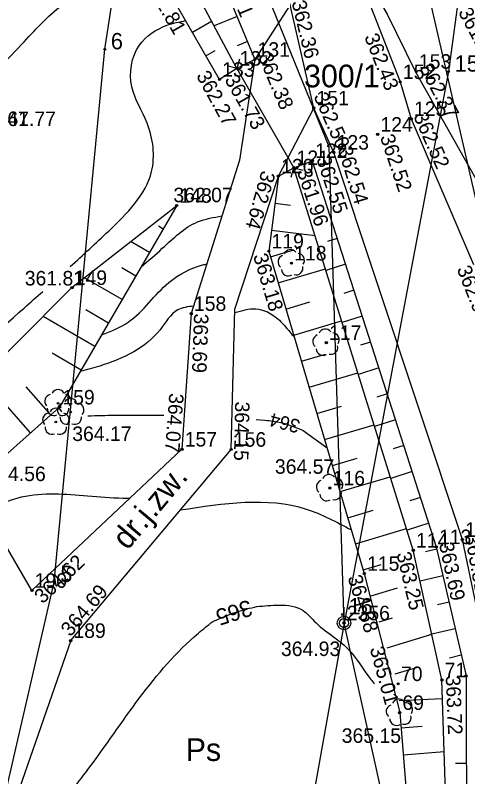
# Model space of a CAD drawing. Extents: x 4635329 to 4651863, y 5356628 to 5367582.
# Drawn here: x 4651721.4 to 4651746.37, y 5357073.31 to 5357115.3 of the extents above; entities that cross this region are included whole.
import ezdxf

# ---------------------------------------------------------------- set-up
doc = ezdxf.new("R2010")
doc.units = 0
for name, color, linetype in [('Level 12', 7, 'Continuous'), ('Level 2', 7, 'Continuous'), ('Level 20', 7, 'Continuous'), ('Level 21', 7, 'Continuous'), ('Level 24', 7, 'Continuous'), ('Level 4', 7, 'Continuous'), ('Level 44', 7, 'Continuous'), ('Level 45', 7, 'Continuous'), ('Level 46', 7, 'Continuous'), ('Level 47', 7, 'Continuous'), ('Level 48', 7, 'Continuous'), ('Level 5', 7, 'Continuous'), ('Level 55', 7, 'Continuous'), ('Level 62', 7, 'Continuous'), ('Level 63', 7, 'Continuous'), ('Level 7', 7, 'Continuous')]:
    doc.layers.add(name, color=color, linetype=linetype)

msp = doc.modelspace()

# ---------------------------------------------------------------- linework, layer by layer
at = {"layer": 'Level 2'}
for p, q in [((4651752.271, 5357081.395), (4651734.633, 5357158.117)), ((4651739.54, 5357082.165), (4651739.54, 5357082.665))]:
    msp.add_line(p, q, dxfattribs=at)
msp.add_circle((4651739.54, 5357081.79), 0.375, dxfattribs=at)
at = {"layer": 'Level 20'}
for p, q in [((4651740.22, 5357117.83), (4651742.64, 5357111.63)), ((4651742.64, 5357111.63), (4651743.25, 5357109.59)), ((4651743.25, 5357109.59), (4651746.68, 5357101.55))]:
    msp.add_line(p, q, dxfattribs=at)
for points in [[(4651729.32, 5357025.03), (4651737.42, 5357039.16), (4651742.88, 5357049.73), (4651744.63, 5357054), (4651745.586, 5357056.87), (4651746.84, 5357061.68), (4651747.431, 5357065.159), (4651747.81, 5357068.95), (4651747.54, 5357079.35), (4651746.07, 5357086.39), (4651738.98, 5357107.74), (4651737.87, 5357110.18), (4651736.57, 5357115.87), (4651735.37, 5357118.93)], [(4651736.57, 5357115.87), (4651734.62, 5357112.86), (4651733.779, 5357107.317), (4651731.11, 5357098.85), (4651730.6, 5357091.37), (4651722.32, 5357083.58)], [(4651724.46, 5357080.82), (4651733.31, 5357091.36), (4651733.521, 5357099.085), (4651735.92, 5357106.43), (4651737.87, 5357110.18)], [(4651722.32, 5357083.58), (4651718.95, 5357089.36)], [(4651724.46, 5357080.82), (4651721.17, 5357071.37)]]:
    msp.add_lwpolyline(points, dxfattribs=at)
at = {"layer": 'Level 24'}
for p, q in [((4651733.769, 5357112.882), (4651733.63, 5357112.37)), ((4651733.63, 5357112.37), (4651733.118, 5357112.509)), ((4651733.63, 5357112.37), (4651736.77, 5357106.89)), ((4651736.631, 5357106.378), (4651736.77, 5357106.89)), ((4651736.77, 5357106.89), (4651737.282, 5357106.751))]:
    msp.add_line(p, q, dxfattribs=at)
at = {"layer": 'Level 4'}
for p, q in [((4651747.779, 5357130.661), (4651745.31, 5357112.19)), ((4651738.719, 5357108.044), (4651734.382, 5357118.748)), ((4651726.34, 5357113.42), (4651726.932, 5357117.207)), ((4651723.55, 5357084.05), (4651726.34, 5357113.42)), ((4651745.31, 5357112.19), (4651739.54, 5357081.79)), ((4651739.54, 5357081.79), (4651738.719, 5357108.044)), ((4651714.1, 5357043.07), (4651723.55, 5357084.05)), ((4651739.54, 5357081.79), (4651731.74, 5357037.85)), ((4651742.153, 5357070.018), (4651739.54, 5357081.79))]:
    msp.add_line(p, q, dxfattribs=at)
at = {"layer": 'Level 44'}
for centre in [(4651734.62, 5357112.86), (4651733.63, 5357112.37), (4651743.52, 5357112.2), (4651732.67, 5357111.76), (4651742.64, 5357111.63), (4651737.87, 5357110.18), (4651743.25, 5357109.59), (4651741.4, 5357108.73), (4651738.98, 5357107.74), (4651737.79, 5357107.28), (4651736.77, 5357106.89), (4651735.92, 5357106.43), (4651730.31, 5357104.81), (4651735.39, 5357102.29), (4651736.64, 5357101.63), (4651724.53, 5357100.28), (4651731.11, 5357098.85), (4651738.56, 5357097.25), (4651723.85, 5357093.69), (4651730.6, 5357091.37), (4651733.31, 5357091.36), (4651738.76, 5357089.23), (4651746.07, 5357086.39), (4651744.63, 5357085.99), (4651743.36, 5357085.8), (4651740.66, 5357084.52), (4651722.32, 5357083.58), (4651739.54, 5357081.79), (4651739.54, 5357081.79), (4651739.54, 5357081.79), (4651739.54, 5357081.79), (4651739.54, 5357081.79), (4651739.54, 5357081.79), (4651724.46, 5357080.82), (4651746.27, 5357078.87), (4651742.53, 5357078.44), (4651744.94, 5357078.65), (4651742.61, 5357076.85)]:
    msp.add_circle(centre, 0.04, dxfattribs=at)
at = {"layer": 'Level 46'}
for p, q in [((4651734.697, 5357093.013), (4651735.173, 5357092.969)), ((4651737.283, 5357092.406), (4651738.608, 5357091.439))]:
    msp.add_line(p, q, dxfattribs=at)
for points in [[(4651715.922, 5357108.895), (4651718.598, 5357110.718), (4651721.751, 5357113.69), (4651723.994, 5357115.873), (4651726.419, 5357117.329), (4651727.935, 5357117.996), (4651728.782, 5357118.194)], [(4651724.435, 5357101.441), (4651726.557, 5357103.402), (4651728.921, 5357106.677), (4651728.679, 5357109.346), (4651727.83, 5357111.348), (4651728.254, 5357113.652), (4651729.77, 5357114.744), (4651730.809, 5357115.004)], [(4651728.346, 5357101.43), (4651729.515, 5357102.448), (4651731.455, 5357103.904), (4651732.807, 5357104.233)], [(4651726.162, 5357097.67), (4651727.635, 5357098.384), (4651729.879, 5357100.568), (4651731.758, 5357101.538), (4651731.973, 5357101.588)], [(4651710.095, 5357097.843), (4651710.307, 5357097.883), (4651713.763, 5357097.458), (4651716.734, 5357096.306), (4651721.888, 5357099.157), (4651722.918, 5357100.066)], [(4651731.239, 5357099.261), (4651730.364, 5357099.051), (4651729.394, 5357097.96), (4651727.939, 5357096.747), (4651726.059, 5357095.958), (4651724.99, 5357095.653)], [(4651733.516, 5357098.902), (4651734.669, 5357099.112), (4651735.881, 5357098.566), (4651736.548, 5357097.838), (4651736.79, 5357097.569)], [(4651729.603, 5357093.229), (4651726.908, 5357093.229), (4651725.408, 5357093.193)], [(4651735.173, 5357092.969), (4651735.639, 5357092.926), (4651737.283, 5357092.406)], [(4651719.746, 5357087.994), (4651721.754, 5357088.741), (4651725.392, 5357088.801), (4651727.332, 5357088.68), (4651727.741, 5357088.68)], [(4651730.506, 5357088.021), (4651737.458, 5357088.073), (4651739.948, 5357086.92)], [(4651732.299, 5357081.873), (4651734.171, 5357082.566), (4651734.736, 5357082.695)], [(4651734.736, 5357082.695), (4651735.959, 5357082.779), (4651737.293, 5357082.475), (4651737.891, 5357081.899), (4651739.771, 5357080.352), (4651741.014, 5357078.684), (4651741.22, 5357078.439)], [(4651723.473, 5357071.251), (4651725.409, 5357073.711), (4651731.503, 5357081.232), (4651732.299, 5357081.873)]]:
    msp.add_spline(points, degree=3, dxfattribs=at)
at = {"layer": 'Level 48'}
for p, q in [((4651731.177, 5357114.362), (4651732.233, 5357114.968)), ((4651733.637, 5357115.238), (4651732.368, 5357114.713)), ((4651734.21, 5357113.852), (4651733.642, 5357113.617)), ((4651731.924, 5357113.061), (4651732.43, 5357113.352)), ((4651735.73, 5357104.942), (4651736.588, 5357104.832)), ((4651729.557, 5357103.513), (4651729.298, 5357103.663)), ((4651735.539, 5357103.454), (4651737.939, 5357103.147)), ((4651728.803, 5357102.216), (4651727.768, 5357102.817)), ((4651739.166, 5357102.996), (4651738.63, 5357102.823)), ((4651735.483, 5357101.977), (4651736.774, 5357102.36)), ((4651739.625, 5357101.568), (4651738.542, 5357101.219)), ((4651728.05, 5357100.919), (4651727.273, 5357101.37)), ((4651735.909, 5357100.539), (4651738.513, 5357101.311)), ((4651727.296, 5357099.622), (4651725.225, 5357100.825)), ((4651740.084, 5357100.139), (4651739.537, 5357099.964)), ((4651736.336, 5357099.101), (4651737.648, 5357099.49)), ((4651726.543, 5357098.325), (4651725.288, 5357099.054)), ((4651725.789, 5357097.028), (4651722.936, 5357098.686)), ((4651740.543, 5357098.711), (4651739.437, 5357098.356)), ((4651736.762, 5357097.663), (4651739.408, 5357098.448)), ((4651741.002, 5357097.283), (4651740.443, 5357097.104)), ((4651725.036, 5357095.731), (4651723.437, 5357096.66)), ((4651737.189, 5357096.225), (4651738.522, 5357096.62)), ((4651741.461, 5357095.855), (4651740.331, 5357095.492)), ((4651722.247, 5357092.273), (4651719.562, 5357095.312)), ((4651737.615, 5357094.787), (4651740.303, 5357095.584)), ((4651723.371, 5357093.266), (4651721.997, 5357094.82)), ((4651741.919, 5357094.427), (4651741.349, 5357094.244)), ((4651738.042, 5357093.349), (4651739.396, 5357093.75)), ((4651738.468, 5357091.911), (4651741.198, 5357092.72)), ((4651742.378, 5357092.999), (4651741.226, 5357092.629)), ((4651742.837, 5357091.571), (4651742.255, 5357091.384)), ((4651738.895, 5357090.473), (4651740.27, 5357090.88)), ((4651739.321, 5357089.034), (4651742.093, 5357089.856)), ((4651743.296, 5357090.143), (4651742.121, 5357089.765)), ((4651743.755, 5357088.715), (4651743.162, 5357088.524)), ((4651739.748, 5357087.596), (4651741.144, 5357088.01)), ((4651744.213, 5357087.287), (4651743.016, 5357086.902)), ((4651740.174, 5357086.158), (4651742.988, 5357086.993)), ((4651744.661, 5357085.855), (4651744.036, 5357085.711)), ((4651740.601, 5357084.72), (4651741.591, 5357085.014)), ((4651744.998, 5357084.394), (4651743.735, 5357084.103)), ((4651741.04, 5357083.286), (4651742.483, 5357083.73)), ((4651745.334, 5357082.932), (4651744.697, 5357082.785)), ((4651741.481, 5357081.852), (4651742.213, 5357082.077)), ((4651745.671, 5357081.47), (4651744.382, 5357081.173)), ((4651741.922, 5357080.418), (4651744.382, 5357081.175)), ((4651746.008, 5357080.008), (4651745.357, 5357079.859)), ((4651742.362, 5357078.985), (4651743.535, 5357079.345)), ((4651742.577, 5357077.511), (4651744.973, 5357077.632)), ((4651742.679, 5357076.015), (4651743.849, 5357076.111)), ((4651742.802, 5357074.52), (4651745.068, 5357074.706)), ((4651746.28, 5357074.038), (4651745.685, 5357074.037))]:
    msp.add_line(p, q, dxfattribs=at)
for points in [[(4651739.34, 5357119.79), (4651741.917, 5357115.357), (4651743.483, 5357112.18), (4651749.82, 5357100.94)], [(4651730.58, 5357118.08), (4651733.63, 5357112.336)], [(4651732.49, 5357118.01), (4651734.62, 5357112.86)], [(4651732.67, 5357111.76), (4651729.4, 5357117.46)], [(4651734.62, 5357112.86), (4651733.63, 5357112.37), (4651732.67, 5357111.76)], [(4651735.92, 5357106.43), (4651736.77, 5357106.89), (4651737.79, 5357107.28)], [(4651737.79, 5357107.28), (4651744.63, 5357085.99), (4651746.27, 5357078.87), (4651746.29, 5357069.02), (4651745.52, 5357061.26), (4651742.88, 5357054.46)], [(4651741.87, 5357054.91), (4651743.95, 5357061.2), (4651745.25, 5357069.08), (4651744.94, 5357078.65), (4651743.36, 5357085.8), (4651736.77, 5357106.89)], [(4651735.92, 5357106.43), (4651735.39, 5357102.29), (4651740.66, 5357084.52), (4651742.61, 5357076.85), (4651743.21, 5357069.57), (4651741.89, 5357061.31), (4651740.55, 5357055.11)], [(4651703.21, 5357089.09), (4651718.35, 5357094.1), (4651724.53, 5357100.28), (4651730.31, 5357104.81)], [(4651730.31, 5357104.81), (4651723.85, 5357093.69), (4651718.95, 5357089.36), (4651717.03, 5357087.37), (4651705.66, 5357084.24)]]:
    msp.add_lwpolyline(points, dxfattribs=at)
at = {"layer": 'Level 55'}
for centre in [(4651736.64, 5357101.63), (4651738.56, 5357097.25), (4651723.764, 5357093.907), (4651724.461, 5357093.421), (4651723.643, 5357092.876), (4651738.76, 5357089.23), (4651742.61, 5357076.85)]:
    msp.add_circle(centre, 0.045, dxfattribs=at)
for centre, start, end in [((4651736.589, 5357102.002), 37.8655, 157.6473), ((4651736.271, 5357101.697), 109.9556, 229.607), ((4651736.978, 5357101.793), 325.8648, 85.6487), ((4651736.463, 5357101.3), 181.9043, 301.61), ((4651736.899, 5357101.359), 253.9073, 13.5587), ((4651738.509, 5357097.622), 37.8655, 157.6473), ((4651738.898, 5357097.413), 325.8648, 85.6487), ((4651738.191, 5357097.317), 109.9556, 229.607), ((4651738.383, 5357096.92), 181.9043, 301.61), ((4651738.819, 5357096.979), 253.9073, 13.5587), ((4651723.407, 5357094.022), 102.1502, 221.8016), ((4651723.764, 5357094.282), 30.1471, 149.8529), ((4651724.12, 5357094.022), 318.1985, 77.8498), ((4651724.461, 5357093.796), 30.1471, 149.8529), ((4651723.543, 5357093.603), 174.1076, 293.8916), ((4651723.643, 5357093.251), 30.1471, 149.8529), ((4651724.105, 5357093.537), 102.1502, 221.8016), ((4651723.984, 5357093.603), 246.1084, 5.8902), ((4651724.818, 5357093.537), 318.1985, 77.8498), ((4651723.286, 5357092.992), 102.1502, 221.8016), ((4651724.241, 5357093.118), 174.1076, 293.8916), ((4651723.999, 5357092.992), 318.1985, 77.8498), ((4651724.682, 5357093.118), 246.1084, 5.8902), ((4651723.422, 5357092.572), 174.1076, 293.8916), ((4651723.863, 5357092.572), 246.1084, 5.8902), ((4651738.709, 5357089.602), 37.8655, 157.6473), ((4651739.098, 5357089.393), 325.8648, 85.6487), ((4651738.391, 5357089.297), 109.9556, 229.607), ((4651739.019, 5357088.959), 253.9073, 13.5587), ((4651738.583, 5357088.9), 181.9043, 301.61), ((4651742.559, 5357077.222), 37.8655, 157.6473), ((4651742.241, 5357076.917), 109.9556, 229.607), ((4651742.948, 5357077.013), 325.8648, 85.6487), ((4651742.433, 5357076.52), 181.9043, 301.61), ((4651742.869, 5357076.579), 253.9073, 13.5587)]:
    msp.add_arc(centre, 0.375, start, end, dxfattribs=at)
at = {"layer": 'Level 62'}
for centre in [(4651726.34, 5357113.42), (4651745.31, 5357112.19), (4651723.55, 5357084.05), (4651739.45, 5357082.26)]:
    msp.add_circle(centre, 0.05, dxfattribs=at)
at = {"layer": 'Level 63'}
for centre in [(4651734.62, 5357112.86), (4651733.63, 5357112.37), (4651743.52, 5357112.2), (4651732.67, 5357111.76), (4651742.64, 5357111.63), (4651737.87, 5357110.18), (4651743.25, 5357109.59), (4651741.4, 5357108.73), (4651738.98, 5357107.74), (4651737.79, 5357107.28), (4651736.77, 5357106.89), (4651735.92, 5357106.43), (4651730.31, 5357104.81), (4651735.39, 5357102.29), (4651736.64, 5357101.63), (4651724.53, 5357100.28), (4651731.11, 5357098.85), (4651738.56, 5357097.25), (4651723.85, 5357093.69), (4651730.6, 5357091.37), (4651733.31, 5357091.36), (4651738.76, 5357089.23), (4651746.07, 5357086.39), (4651744.63, 5357085.99), (4651743.36, 5357085.8), (4651740.66, 5357084.52), (4651722.32, 5357083.58), (4651739.54, 5357081.79), (4651739.54, 5357081.79), (4651739.54, 5357081.79), (4651739.54, 5357081.79), (4651739.54, 5357081.79), (4651739.54, 5357081.79), (4651724.46, 5357080.82), (4651746.27, 5357078.87), (4651742.53, 5357078.44), (4651744.94, 5357078.65), (4651742.61, 5357076.85)]:
    msp.add_circle(centre, 0.06, dxfattribs=at)
at = {"layer": 'Level 7'}
msp.add_circle((4651739.54, 5357081.79), 0.25, dxfattribs=at)

# ---------------------------------------------------------------- texts
at = {"layer": 'Level 12'}
msp.add_text('Ps', height=1.25, dxfattribs=at).set_placement((4651730.808, 5357074.185))
at = {"layer": 'Level 21'}
msp.add_text('dr.j.zw.', height=1.25, rotation=49.9812, dxfattribs=at).set_placement((4651727.594, 5357085.762))
at = {"layer": 'Level 45'}
for s, rotation, p in [('362.01', 292.5802, (4651732.591, 5357118.141)), ('361.81', 299.8433, (4651728.55, 5357116.995)), ('362.36', 283.4045, (4651736.644, 5357116.025)), ('361.90', 298.0066, (4651745.82, 5357115.477)), ('362.43', 291.4894, (4651740.646, 5357114.114)), ('362.38', 292.8028, (4651734.783, 5357113.031)), ('362.37', 298.3952, (4651743.669, 5357112.38)), ('362.27', 298.7971, (4651731.363, 5357111.97)), ('361.73', 299.6637, (4651732.925, 5357111.752)), ('362.50', 293.8537, (4651737.845, 5357110.836)), ('362.52', 293.7851, (4651743.349, 5357109.743)), ('362.52', 288.6135, (4651741.515, 5357108.589)), ('362.54', 287.1321, (4651739.184, 5357107.93)), ('362.55', 288.1825, (4651738.003, 5357107.39)), ('362.64', 253.9851, (4651735.001, 5357106.777)), ('361.96', 288.1543, (4651736.936, 5357106.7)), ('363.18', 286.4293, (4651734.516, 5357102.041)), ('362.97', 291.4587, (4651745.747, 5357101.319)), ('363.69', 267.9606, (4651731.267, 5357098.862)), ('364.07', 265.6562, (4651729.905, 5357094.483)), ('364.15', 268.7625, (4651733.533, 5357094.009)), ('363.81', 280.4303, (4651746.199, 5357086.616)), ('363.69', 282.1308, (4651744.774, 5357086.155)), ('363.25', 283.3157, (4651742.427, 5357085.618)), ('364.62', 43.1705, (4651722.911, 5357082.812)), ('364.68', 287.246, (4651739.731, 5357084.304)), ('364.69', 49.6034, (4651724.444, 5357080.993)), ('365.01', 285.2533, (4651740.955, 5357080.381)), ('363.72', 272.3884, (4651745.148, 5357078.881))]:
    msp.add_text(s, height=0.8, rotation=rotation, dxfattribs=at).set_placement(p)
for s, p in [('361.77', (4651720.37, 5357109.19)), ('362.07', (4651730.126, 5357104.99)), ('361.81', (4651721.925, 5357100.4)), ('364.17', (4651724.545, 5357091.825)), ('364.57', (4651735.727, 5357090.017)), ('364.56', (4651719.812, 5357089.616)), ('364.93', (4651736.059, 5357079.97)), ('365.15', (4651739.413, 5357075.182))]:
    msp.add_text(s, height=0.8, dxfattribs=at).set_placement(p)
at = {"layer": 'Level 47'}
for s, height, rotation, p in [('364', 0.75, 165.2188, (4651737.17, 5357092.963)), ('365', 0.9, 197.5044, (4651734.3, 5357083.091))]:
    msp.add_text(s, height=height, rotation=rotation, dxfattribs=at).set_placement(p)
at = {"layer": 'Level 5'}
msp.add_text('300/1', height=1.25, dxfattribs=at).set_placement((4651737.337, 5357111.324))
at = {"layer": 'Level 62'}
for s, p in [(' 6', (4651726.34, 5357113.42)), (' 15', (4651745.31, 5357112.19)), (' 5', (4651723.55, 5357084.05)), (' 16', (4651739.45, 5357082.26))]:
    msp.add_text(s, height=0.9, dxfattribs=at).set_placement(p)
at = {"layer": 'Level 63'}
for s, p in [('131', (4651734.77, 5357113.01)), ('132', (4651733.78, 5357112.52)), ('153', (4651743.67, 5357112.35)), ('133', (4651732.82, 5357111.91)), ('152', (4651742.79, 5357111.78)), ('151', (4651738.02, 5357110.33)), ('125', (4651743.4, 5357109.74)), ('147', (4651720.37, 5357109.19)), ('124', (4651741.55, 5357108.88)), ('123', (4651739.13, 5357107.89)), ('122', (4651737.94, 5357107.43)), ('121', (4651736.92, 5357107.04)), ('120', (4651736.07, 5357106.58)), ('148', (4651730.46, 5357104.96)), ('119', (4651735.54, 5357102.44)), ('118', (4651736.79, 5357101.78)), ('149', (4651724.68, 5357100.43)), ('158', (4651731.26, 5357099)), ('117', (4651738.71, 5357097.4)), ('159', (4651724, 5357093.84)), ('157', (4651730.75, 5357091.52)), ('156', (4651733.46, 5357091.51)), ('116', (4651738.91, 5357089.38)), ('112', (4651746.22, 5357086.54)), ('113', (4651744.78, 5357086.14)), ('114', (4651743.51, 5357085.95)), ('115', (4651740.81, 5357084.67)), ('190', (4651722.47, 5357083.73)), ('2356', (4651739.69, 5357081.94)), ('2356', (4651739.69, 5357081.94)), ('2356', (4651739.69, 5357081.94)), ('2356', (4651739.69, 5357081.94)), ('2356', (4651739.69, 5357081.94)), ('2356', (4651739.69, 5357081.94)), ('189', (4651724.61, 5357080.97)), ('70', (4651742.68, 5357078.59)), ('71', (4651745.09, 5357078.8)), ('69', (4651742.76, 5357077))]:
    msp.add_text(s, height=0.8, dxfattribs=at).set_placement(p)

doc.saveas('drawing.dxf')
